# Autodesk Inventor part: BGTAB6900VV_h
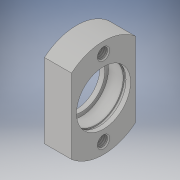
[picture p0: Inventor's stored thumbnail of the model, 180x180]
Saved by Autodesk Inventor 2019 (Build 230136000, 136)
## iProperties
Created: 2022-11
Part Number: BGTAB6900VV_h
Material: Generic
Catalog Web Link: www.cadenas.de
Description: BGTAB, BGTCA, SBGTA_housing-Bearings with Housings - Space Saving, Small Flange - Retained
Vendor: MISUMI
Document SubType Name: Modeling
Designer: psAdmin
Manufacturer: MISUMI
Mass: 6.24417 g
Surface Area: 36.8237 cm^2
Volume: 6.24417 cm^3
Density: 1 g/cm^3
Appearance: PSOLRGB-175-175-175
Category: PARTsolutions
Company: MISUMI
Title: BGTAB6900VV
Author: Cadenas PARTsolutions
Comments: Bearings with Housings - Space Saving, Small Flange - Retained
PSOL_IDENT_0: {$CADENAS_DATA/23d-libs/misumi/metric/12_bearing_holders/bgtab/housing_bgtab.prj},202 {VTYP=3D},{NB=
PSOL_IDENT_1: BGTAB6900VV_h},{LINA=BGTAB6900VV},{NN=BGTAB, BGTCA, SBGTA_housing},{DATE=25.04.2017 02:57:07},{GEOMD
PSOL_IDENT_2: ATE=10.07.2015 02:13:07},{VERSION=},{LINEID=90},{WBVAR=MATB,ST,SEAL,ALT1},{WBNUMERIC=}  {NB=BGTAB690
PSOL_IDENT_3: 0VV_h},{LINA=BGTAB6900VV},{KT=DUMMY},{PN=BGTAB6900VV},{TYPE=BGTAB},{MATB=S},{MATBALG= 'S' , 'Steel'
PSOL_IDENT_4: , 'SS' , 'Stainless Steel' },{ST=BO},{STALG= 'BO' , 'Black Oxide' , 'ENP' , 'Electroless Nickel Plat
PSOL_IDENT_5: ing' },{BN=6900},{SEAL=VV},{SEALALG= 'ZZ' , 'Double Shielded' , 'VV' , 'Non-Contact Sealed Rubber Se
PSOL_IDENT_6: al' , 'DD' , 'Contact Sealed Rubber Seal' },{DD=10},{D=22},{B=6},{H=40},{W=26},{T=11},{DDHH=19},{A=3
PSOL_IDENT_7: 1},{F=0},{M=M5},{ALT1=},{M3D=5},{MM=1.15},{BDD2=23}
NB: BGTAB6900VV_h
NN: BGTAB, BGTCA, SBGTA_housing
NT: Bearings with Housings - Space Saving, Small Flange - Retained
NBSYN: $PN._h
LINA: BGTAB6900VV
CATALOG: Misumi
PN: BGTAB6900VV
MATB: Steel
ST: Black Oxide
BN: 6900
SEAL: Non-Contact Sealed Rubber Seal
DD: 10
D: 22
B: 6
H: 40
W: 26
T: 11
DDHH: 19
A: 31
F: 0
M: M5
ALT1: Bearing and Retaining Ring Assembled
SUPPLIER: MISUMI
ARTICLENO: BGTAB6900VV_h
BOMINFO: BGTAB6900VV
CREATOR: CADENAS GmbH
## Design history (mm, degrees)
sketch "Sketch_1"
  geometry: L1 (-13, 15.199)-(-13, -15.199); L2 (13, -15.199)-(13, 15.199); A1 r 20 centre (0, 0) between (-13, -15.199) and (13, -15.199); A2 r 20 centre (0, 0) between (13, 15.199) and (-13, 15.199)
  constraints: 4 end point, 4 point on circle, 2 centre point
extrude "Extrusion1" join sketch "Sketch_1" stored distance "d0" = 11; taper "d1" = 0 deg
sketch "Sketch2"
  geometry: 1 further point
hole "Hole1" sketch "Sketch2" at (0, 0) diameter "d2" = 19; stored, may be unused: countersink angle "d6" = 90 deg, drill point angle "d8" = 0 deg; dims "d3" = 6, "d4" = 22, "d5" = 9, "d7" = 11
sketch "Sketch_9"
  geometry: L1 (3.65, 0)-(2.5, 0); L2 (2.5, 0)-(2.5, 11.5); L3 (2.5, 11.5)-(3.65, 11.5); L4 (3.65, 11.5)-(3.65, 0); L5 (3.65, 0)-(2.5, 0)
  constraints: 10 end point
revolve "Revolution1" sketch "Sketch_9" stored, may be unused: angle "d9" = 360 deg
sketch "Sketch_8"
  geometry: L1 (5.5, -15.5)-(-5.5, -15.5); L2 (-5.5, -15.5)-(-5.5, -13); L3 (-5.5, -13)-(-5.067, -13.433); L4 (-5.067, -13.433)-(5.067, -13.433); L5 (5.067, -13.433)-(5.5, -13); L6 (5.5, -13)-(5.5, -15.5); L7 (5.5, -15.5)-(-5.5, -15.5)
  constraints: 14 end point
revolve "Revolution2" sketch "Sketch_8" stored, may be unused: angle "d10" = 360 deg
thread "Thread1" dims "d11" = 10.134, "d12" = 0
sketch "Sketch_2"
  geometry: L1 (5.5, 15.5)-(-5.5, 15.5); L2 (-5.5, 15.5)-(-5.5, 18); L3 (-5.5, 18)-(-5.067, 17.567); L4 (-5.067, 17.567)-(5.067, 17.567); L5 (5.067, 17.567)-(5.5, 18); L6 (5.5, 18)-(5.5, 15.5); L7 (5.5, 15.5)-(-5.5, 15.5)
  constraints: 14 end point
revolve "Revolution3" sketch "Sketch_2" stored, may be unused: angle "d13" = 360 deg
thread "Thread2" dims "d14" = 10.134, "d15" = 0
node "HOUSING_TO_DUMMY_XY"
node "HOUSING_TO_DUMMY_YZ"
node "HOUSING_TO_DUMMY_ZX"
node "HOUSING_TO_DUMMY_X"
node "HOUSING_TO_DUMMY_Y"
node "HOUSING_TO_DUMMY_Z"
node "HOUSING_TO_DUMMY_Center"
node "bgcab_to_rring_XY"
node "bgcab_to_rring_YZ"
node "bgcab_to_rring_ZX"
node "bgcab_to_rring_X"
node "bgcab_to_rring_Y"
node "bgcab_to_rring_Z"
node "bgcab_to_rring_Center"
node "to_bearings_XY"
node "to_bearings_YZ"
node "to_bearings_ZX"
node "to_bearings_X"
node "to_bearings_Y"
node "to_bearings_Z"
node "to_bearings_Center"
body "Solid1"
other parameters: "d16" = 0, "d17" = 0
